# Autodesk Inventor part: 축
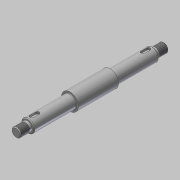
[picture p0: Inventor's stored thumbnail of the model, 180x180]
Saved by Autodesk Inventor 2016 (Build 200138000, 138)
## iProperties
Created: 2018-11
Part Number: 축
Material: 강철, 연강
Document SubType Name: Modeling
Designer: mduedu
Density: 1 g/cm^3
Appearance: 강철
Author: mduedu
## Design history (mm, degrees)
sketch "스케치1"
  geometry: L1 (-26, 0)-(26, 0); L2 (26, 0)-(26, 11); L3 (26, 11)-(-26, 11); L4 (-26, 11)-(-26, 0); L5 (-26, 0)-(-81, 0); L6 (-81, 0)-(-81, 8.5); L7 (-81, 8.5)-(-26, 8.5); L8 (-26, 8.5)-(-26, 0); L9 (-81, 0)-(-96, 0); L10 (-96, 0)-(-96, 6); L11 (-96, 6)-(-81, 6); L12 (-81, 6)-(-81, 0); L13 (0, 0)-(0, 11); L14 (26, 0)-(81, 0); L15 (81, 0)-(81, 8.5); L16 (81, 8.5)-(26, 8.5); L17 (26, 8.5)-(26, 0); L18 (81, 0)-(96, 0); L19 (96, 0)-(96, 6); L20 (96, 6)-(81, 6); L21 (81, 6)-(81, 0); 1 further point
  constraints: 42 end point, 6 parallel, 6 symmetric about line, 3 horizontal, 3 perpendicular, 2 midpoint, 1 coincident
  dimensions: "d0" = 22 diameter of L3 L1; "d2" = 17 diameter of L7 L5; "d3" = 12 diameter of L11 L9; "d4" = 52 distance of L2.end L3.end; "d5" = 55 distance of L6.end L7.end; "d6" = 192 distance between parallel lines of L19 L10
revolve "회전1" sketch "스케치1" stored, may be unused: angle "d7" = 90 deg
fillet "모깎기1" dims "d8" = 0.6
node "작업 평면1"
sketch "스케치2" dims "d11" = 12
  geometry: L1 (15, 2.5)-(22, 2.5); L2 (22, 2.5)-(22, -2.5); L3 (22, -2.5)-(15, -2.5); L4 (15, -2.5)-(15, 2.5); L5 (27.5, 8.5)-(27.5, -8.5) reference; 3 further points
  constraints: 8 end point, 2 midpoint, 2 parallel, 2 vertical alignment, 1 horizontal, 1 horizontal alignment, 1 perpendicular, 4 other
  dimensions: "d9" = 3 dimension on L5; "d10" = 5 distance between parallel lines of L3 L1
extrude "돌출1" cut sketch "스케치2" distance "d12" = 3; taper "d13" = 0 deg
chamfer "모따기1" distance "d14" = 1; stored, may be unused: second distance "d15" = 2, angle "d16" = 45 deg
feature "스레드1" dims "d17" = 12, "d18" = 0
feature "스레드2" dims "d19" = 12, "d20" = 0
chamfer "모따기2" distance "d21" = 1; stored, may be unused: second distance "d22" = 2, angle "d23" = 45 deg
node "솔리드1"
mirror "대칭1"
